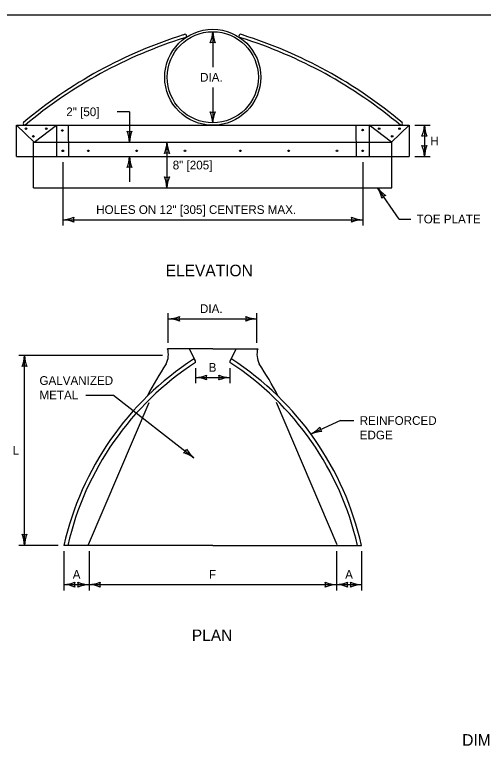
# Model space of a CAD drawing. Extents: x 49991.4 to 50021, y 49987.6 to 50011.4.
# Drawn here: x 50006.92 to 50010.14, y 49993.85 to 49999 of the extents above; entities that cross this region are included whole.
import ezdxf

# ---------------------------------------------------------------- set-up
doc = ezdxf.new("R2010")
doc.units = 0
for name, color, linetype in [('Level 1', 7, 'Continuous'), ('Level 2', 7, 'Continuous'), ('Level 3', 7, 'Continuous'), ('Level 4', 7, 'Continuous')]:
    doc.layers.add(name, color=color, linetype=linetype)

msp = doc.modelspace()

# ---------------------------------------------------------------- linework, layer by layer
at = {"layer": 'Level 1'}
for p, q in [((50008.075, 49998.8609), (50008.0881, 49998.8666)), ((50008.0847, 49998.8408), (50008.0975, 49998.8462)), ((50008.4743, 49998.8409), (50008.4619, 49998.8462)), ((50008.4845, 49998.8609), (50008.4713, 49998.8667)), ((50008.4845, 49998.8609), (50008.4713, 49998.8667)), ((50006.9262, 49998.022), (50006.9262, 49998.2377)), ((50006.9262, 49998.2377), (50009.6333, 49998.2377)), ((50006.9262, 49998.2377), (50007.0471, 49998.1203)), ((50007.0471, 49998.1203), (50007.2008, 49998.2377)), ((50007.2008, 49998.2377), (50007.2016, 49998.0234)), ((50009.3586, 49998.2377), (50009.3575, 49998.0234)), ((50009.5123, 49998.1203), (50009.3586, 49998.2377)), ((50009.6333, 49998.2377), (50009.5123, 49998.1203)), ((50009.6333, 49998.2377), (50009.6333, 49998.022)), ((50006.9262, 49998.022), (50009.6333, 49998.022)), ((50008.2793, 49996.6959), (50007.968, 49996.6959)), ((50008.1171, 49996.6959), (50008.1593, 49996.6135)), ((50008.2793, 49996.6959), (50008.5902, 49996.6959)), ((50008.4416, 49996.6959), (50008.3991, 49996.6135)), ((50007.4216, 49995.345), (50007.84, 49996.3253)), ((50009.1374, 49995.3433), (50008.7185, 49996.3253)), ((50007.2798, 49995.339), (50007.253, 49995.339)), ((50008.2793, 49995.339), (50007.253, 49995.339)), ((50008.2793, 49995.339), (50009.2782, 49995.339)), ((50009.2784, 49995.339), (50009.3052, 49995.339))]:
    msp.add_line(p, q, dxfattribs=at)
msp.add_lwpolyline([(49999.3835, 49998.9992), (50016.7501, 49998.9992), (50016.7501, 49987.7988), (49999.3835, 49987.7988)], close=True, dxfattribs=at)
for centre, radius in [((50008.2797, 49998.569), 0.3313), ((50008.2798, 49998.569), 0.3144), ((50006.9914, 49998.2141), 0.0054), ((50007.1316, 49998.2141), 0.0054), ((50009.4278, 49998.2141), 0.0054), ((50009.568, 49998.2141), 0.0054), ((50007.0421, 49998.1611), 0.0054), ((50007.2428, 49998.202), 0.0054), ((50009.3132, 49998.205), 0.0054), ((50009.5173, 49998.1611), 0.0054), ((50007.2455, 49998.0612), 0.0054), ((50007.422, 49998.0612), 0.0054), ((50007.7555, 49998.0612), 0.0054), ((50008.0889, 49998.0612), 0.0054), ((50008.4704, 49998.0612), 0.0054), ((50008.8039, 49998.0612), 0.0054), ((50009.1374, 49998.0612), 0.0054), ((50009.3139, 49998.0612), 0.0054)]:
    msp.add_circle(centre, radius, dxfattribs=at)
for centre, radius, start, end in [((50009.034, 49995.8071), 3.2008, 107.4341, 130.0619), ((50009.038, 49995.7986), 3.1881, 107.3993, 130.0872), ((50008.0852, 49998.8529), 0.014, 331.5314, 77.9349), ((50008.4742, 49998.8529), 0.014, 102.0651, 208.4686), ((50007.5213, 49995.7986), 3.1881, 49.9128, 72.6075), ((50007.5254, 49995.8074), 3.2006, 49.9347, 72.5611), ((50006.9846, 49998.2502), 0.0125, 148.1922, 272.1376), ((50009.5748, 49998.2502), 0.0125, 267.8624, 31.8078), ((50009.5748, 49998.2502), 0.0125, 267.8624, 31.8078), ((50007.8334, 49996.6563), 0.1404, 332.1165, 16.4834), ((50008.7249, 49996.6563), 0.1404, 163.5166, 207.8835), ((50009.2791, 49994.8822), 2.077, 123.0384, 167.2954), ((50008.1423, 49996.6046), 0.0192, 349.5581, 76.5269), ((50008.416, 49996.6046), 0.0192, 103.4731, 190.4419), ((50007.2792, 49994.8822), 2.077, 12.7046, 56.9616), ((50009.2791, 49994.8822), 2.0505, 123.0384, 167.1285), ((50010.1574, 49995.1555), 2.6267, 146.8806, 152.4206), ((50007.2792, 49994.8822), 2.0505, 12.8715, 56.9616), ((50006.4009, 49995.1555), 2.6267, 27.5794, 33.1194)]:
    msp.add_arc(centre, radius, start, end, dxfattribs=at)
at = {"layer": 'Level 3'}
for p, q in [((50008.2795, 49998.8833), (50008.2795, 49998.639)), ((50008.2795, 49998.499), (50008.2795, 49998.2546)), ((50007.7053, 49998.3306), (50007.6201, 49998.3306)), ((50007.7053, 49998.3306), (50007.7053, 49998.1201)), ((50009.6733, 49998.2377), (50009.7797, 49998.2377)), ((50009.7397, 49998.2377), (50009.7397, 49998.022)), ((50007.9634, 49998.1201), (50007.9634, 49997.8061)), ((50007.7053, 49998.022), (50007.7053, 49997.8485)), ((50009.6733, 49998.022), (50009.7797, 49998.022)), ((50007.2455, 49997.982), (50007.2455, 49997.5458)), ((50009.3139, 49997.982), (50009.3139, 49997.5458)), ((50009.5647, 49997.5906), (50009.4164, 49997.806)), ((50007.2455, 49997.5858), (50009.3139, 49997.5858)), ((50009.5647, 49997.5906), (50009.6461, 49997.5906)), ((50007.9732, 49996.7359), (50007.9732, 49996.9422)), ((50008.5848, 49996.7359), (50008.5848, 49996.9422)), ((50007.9732, 49996.9022), (50008.5848, 49996.9022)), ((50007.9336, 49996.6488), (50006.9411, 49996.6488)), ((50006.9811, 49995.339), (50006.9811, 49996.6488)), ((50008.1611, 49996.5611), (50008.1611, 49996.457)), ((50008.3969, 49996.5611), (50008.3969, 49996.457)), ((50008.1611, 49996.497), (50008.3969, 49996.497)), ((50007.4036, 49996.3763), (50007.5946, 49996.3763)), ((50007.5946, 49996.3763), (50008.1488, 49995.9438)), ((50009.1605, 49996.2002), (50008.9564, 49996.1073)), ((50009.1605, 49996.2002), (50009.2534, 49996.2002)), ((50007.213, 49995.339), (50006.9411, 49995.339)), ((50007.253, 49995.299), (50007.253, 49995.0282)), ((50007.4261, 49995.299), (50007.4261, 49995.0282)), ((50009.1323, 49995.299), (50009.1322, 49995.0282)), ((50009.3052, 49995.299), (50009.3051, 49995.0282)), ((50007.253, 49995.0682), (50007.4261, 49995.0682)), ((50007.4261, 49995.0682), (50009.1322, 49995.0682)), ((50009.1322, 49995.0682), (50009.3051, 49995.0682))]:
    msp.add_line(p, q, dxfattribs=at)
for centre, radius, start, end in [((50008.0574, 49998.8925), 0.2223, 337.456, 357.6395), ((50008.5123, 49998.8948), 0.233, 182.8273, 202.0772), ((50008.2795, 49998.7551), 0.0548, 72.1388, 107.8612), ((50008.2795, 49998.3828), 0.0548, 252.1388, 287.8612), ((50008.0468, 49998.2431), 0.233, 2.8273, 22.0772), ((50008.5017, 49998.2454), 0.2223, 157.456, 177.6395), ((50009.5176, 49998.2468), 0.2223, 337.456, 357.6395), ((50009.9725, 49998.2491), 0.233, 182.8273, 202.0772), ((50007.7053, 49998.2483), 0.0548, 252.1388, 287.8612), ((50007.4726, 49998.1086), 0.233, 2.8273, 22.0772), ((50007.9275, 49998.1109), 0.2223, 157.456, 177.6395), ((50007.7413, 49998.1292), 0.2223, 337.456, 357.6395), ((50008.1962, 49998.1315), 0.233, 182.8273, 202.0772), ((50009.7397, 49998.1094), 0.0548, 72.1388, 107.8612), ((50009.7397, 49998.1502), 0.0548, 252.1388, 287.8612), ((50009.507, 49998.0105), 0.233, 2.8273, 22.0772), ((50009.9619, 49998.0128), 0.2223, 157.456, 177.6395), ((50007.4832, 49998.0311), 0.2223, 337.456, 357.6395), ((50007.9381, 49998.0334), 0.233, 182.8273, 202.0772), ((50007.9634, 49997.9918), 0.0548, 72.1388, 107.8612), ((50007.7053, 49997.8937), 0.0548, 72.1388, 107.8612), ((50007.9634, 49997.9343), 0.0548, 252.1388, 287.8612), ((50007.7307, 49997.7946), 0.233, 2.8273, 22.0772), ((50008.1856, 49997.7969), 0.2223, 157.456, 177.6395), ((50009.2282, 49997.6876), 0.2223, 11.998, 32.1815), ((50009.6016, 49997.9475), 0.233, 217.3693, 236.6192), ((50009.4891, 49997.7004), 0.0548, 106.6808, 142.4032), ((50007.234, 49997.8185), 0.233, 272.8273, 292.0772), ((50007.3737, 49997.5858), 0.0548, 162.1388, 197.8612), ((50007.2363, 49997.3636), 0.2223, 67.456, 87.6395), ((50007.9617, 49997.1349), 0.233, 272.8273, 292.0772), ((50007.964, 49996.6801), 0.2223, 67.456, 87.6395), ((50008.1014, 49996.9022), 0.0548, 162.1388, 197.8612), ((50008.5939, 49997.1243), 0.2223, 247.456, 267.6395), ((50008.4566, 49996.9022), 0.0548, 342.1388, 17.8612), ((50008.5963, 49996.6695), 0.233, 92.8273, 112.0772), ((50006.759, 49996.658), 0.2223, 337.456, 357.6395), ((50007.2138, 49996.6603), 0.233, 182.8273, 202.0772), ((50006.9811, 49996.5206), 0.0548, 72.1388, 107.8612), ((50008.1496, 49996.7297), 0.233, 272.8273, 292.0772), ((50008.1519, 49996.2749), 0.2223, 67.456, 87.6395), ((50008.2893, 49996.497), 0.0548, 162.1388, 197.8612), ((50008.406, 49996.7191), 0.2223, 247.456, 267.6395), ((50008.2687, 49996.497), 0.0548, 342.1388, 17.8612), ((50008.4084, 49996.2643), 0.233, 92.8273, 112.0772), ((50008.8495, 49996.3143), 0.233, 297.3082, 316.558), ((50009.0401, 49995.9014), 0.2223, 91.9369, 112.1204), ((50009.0731, 49996.1604), 0.0548, 186.6197, 222.3421), ((50008.0475, 49996.0224), 0.0548, 304.3531, 340.0754), ((50008.2921, 49996.1138), 0.2223, 209.6703, 229.8538), ((50008.0153, 49995.7529), 0.233, 55.0416, 74.2914), ((50006.9811, 49995.4672), 0.0548, 252.1388, 287.8612), ((50006.7484, 49995.3275), 0.233, 2.8273, 22.0772), ((50007.2032, 49995.3299), 0.2223, 157.456, 177.6395), ((50007.2415, 49995.3009), 0.233, 272.8273, 292.0772), ((50007.3812, 49995.0682), 0.0548, 162.1388, 197.8612), ((50007.4352, 49995.2903), 0.2223, 247.456, 267.6395), ((50007.2979, 49995.0682), 0.0548, 342.1388, 17.8612), ((50007.4146, 49995.3009), 0.233, 272.8273, 292.0772), ((50007.5543, 49995.0682), 0.0548, 162.1388, 197.8612), ((50009.1413, 49995.2903), 0.2223, 247.456, 267.6395), ((50009.004, 49995.0682), 0.0548, 342.1388, 17.8612), ((50009.1207, 49995.3009), 0.233, 272.8273, 292.0772), ((50009.2604, 49995.0682), 0.0548, 162.1388, 197.8612), ((50009.3142, 49995.2903), 0.2223, 247.456, 267.6395), ((50009.1769, 49995.0682), 0.0548, 342.1388, 17.8612), ((50007.2438, 49994.8461), 0.2223, 67.456, 87.6395), ((50007.4376, 49994.8355), 0.233, 92.8273, 112.0772), ((50007.4169, 49994.8461), 0.2223, 67.456, 87.6395), ((50009.1437, 49994.8355), 0.233, 92.8273, 112.0772), ((50009.123, 49994.8461), 0.2223, 67.456, 87.6395), ((50009.3166, 49994.8355), 0.233, 92.8273, 112.0772)]:
    msp.add_arc(centre, radius, start, end, dxfattribs=at)
for centre, major_axis, start_param, end_param in [((50009.3232, 49997.8079), (-0.2245, 0), 1.177329, 1.529598), ((50009.1845, 49997.5858), (0.0553, 0), 5.971449, 6.594922), ((50009.3255, 49997.353), (-0.2352, 0), 4.761735, 5.097708)]:
    msp.add_ellipse(centre, major_axis=major_axis, ratio=0.990431, start_param=start_param, end_param=end_param, dxfattribs=at)
at = {"layer": 'Level 4'}
for p, q in [((50007.2831, 49998.2369), (50007.2839, 49998.0223)), ((50009.2667, 49998.2377), (50009.2677, 49998.022)), ((50007.0439, 49997.8061), (50007.0439, 49998.1201)), ((50007.0439, 49998.1201), (50009.5155, 49998.1201)), ((50009.5155, 49997.8061), (50009.5155, 49998.1201)), ((50007.0439, 49997.8061), (50009.5155, 49997.8061))]:
    msp.add_line(p, q, dxfattribs=at)

# ---------------------------------------------------------------- texts
at = {"layer": 'Level 2'}
for s, height, p in [('DIA.', 0.06, (50008.1921, 49998.539)), ('2" [50]', 0.06, (50007.2691, 49998.3006)), ('H', 0.06, (50009.7797, 49998.0998)), ('8" [205]', 0.06, (50008.0034, 49997.9331)), ('HOLES ON 12" [305] CENTERS MAX.', 0.06, (50007.4754, 49997.6258)), ('TOE PLATE', 0.06, (50009.6861, 49997.5606)), ('ELEVATION', 0.08, (50007.9552, 49997.1957)), ('DIA.', 0.06, (50008.1915, 49996.9422)), ('B', 0.06, (50008.2513, 49996.537)), ('GALVANIZED', 0.06, (50007.0842, 49996.4463)), ('METAL', 0.06, (50007.0842, 49996.3463)), ('REINFORCED', 0.06, (50009.2934, 49996.1702)), ('EDGE', 0.06, (50009.2934, 49996.0702)), ('L', 0.06, (50006.8987, 49995.9639)), ('A', 0.06, (50007.3137, 49995.1082)), ('F', 0.06, (50008.2529, 49995.1082)), ('A', 0.06, (50009.1929, 49995.1082)), ('PLAN', 0.08, (50008.1353, 49994.6782)), ('DIMENSION TABLE', 0.08, (50010.0003, 49993.9561))]:
    msp.add_text(s, height=height, dxfattribs=at).set_placement(p)

doc.saveas('drawing.dxf')
